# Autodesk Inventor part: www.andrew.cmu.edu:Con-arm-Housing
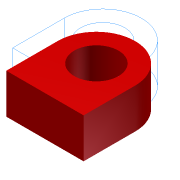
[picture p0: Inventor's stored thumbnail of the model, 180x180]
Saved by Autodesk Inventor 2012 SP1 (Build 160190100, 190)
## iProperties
Shininess: 64.0
Angle Display Precision: 2
Document Length Units: 11272
Document Angle Units: 11279
Document Time Units: 11290
Document Mass Units: 11283
Document Length Units Precision: 3
Document Angle Units Precision: 2
Created: 2008-04
Document SubType Name: Modeling
Density: 7.86 g/cm^3
Mass: 284.501 g
Surface Area: 89.549 cm^2
Volume: 36.1961 cm^3
Material: Steel, Mild
Density: 0.0
Volumn: 0.0
Area: 0.0
PropertySet Name: Model Information
Control State: 0
Master: False
Checked Out: False
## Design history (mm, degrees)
sketch "Sketch1"
  geometry: L1 (22.225, 3.67)-(22.225, -25.895); L2 (22.225, -25.895)-(-22.225, -25.895); L3 (-22.225, 3.67)-(-22.225, -25.895); A1 r 22.225 centre (0, 3.67) between (22.225, 3.67) and (-22.225, 3.67)
  constraints: 6 end point, 2 point on circle, 2 tangent, 2 vertical, 1 centre point, 1 horizontal, 1 other
  dimensions: "d1" = 44.45 distance of L1.end L2.end; "d3" = 29.5656 distance of L3.start L2.end
extrude "ExtrusionMidplane1" new body sketch "Sketch1" stored distance "d4" = 22.86; taper "d5" = 0 deg
sketch "Sketch2"
  geometry: C1 r 12.7 at (0, 3.67); A1 r 22.225 centre (0, 3.67) between (22.225, 3.67) and (-22.225, 3.67) reference
  constraints: 1 centre point, 1 concentric
  dimensions: "d7" = 25.4 diameter of C1
extrude "ExtrusionBlind1" cut sketch "Sketch2" stored distance "d8" = 38.1; taper "d9" = 0 deg
body "Solid1"
other parameters: "d0" = 44.45 (derived), "d2" = 29.5656 (derived), "d6" = 25.4 (derived)
